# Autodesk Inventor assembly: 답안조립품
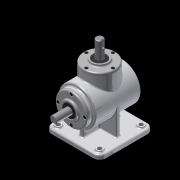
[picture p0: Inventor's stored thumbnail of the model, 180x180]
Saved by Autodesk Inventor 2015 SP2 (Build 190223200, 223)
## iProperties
Created: 2015-07
Part Number: 답안조립품
Document SubType Name: Assembly
Designer: AMC
Author: AMC
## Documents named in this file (14)
- C:\Users\AMC\Desktop\450705V1025\답안조립품.iam
- C:\Users\AMC\Desktop\450705V1025\본체.ipt
- C:\Users\AMC\Desktop\450705V1025\커버.ipt
- C:\Users\AMC\Desktop\450705V1025\베어링 6203.ipt
- C:\Users\AMC\Desktop\450705V1025\메인 베벨기어.ipt
- C:\Users\AMC\Desktop\450705V1025\메인 축.ipt
- 메인 축.ipt
- C:\Users\AMC\Desktop\450705V1025\키 5x5.ipt
- C:\Users\AMC\Desktop\450705V1025\서브 베벨기어.ipt
- C:\Users\AMC\Desktop\450705V1025\서브 축.ipt
- 서브 축.ipt
- C:\Users\AMC\Desktop\450705V1025\키 4x4.ipt
- C:\Users\AMC\Desktop\450705V1025\오일실.ipt
- C:\Users\AMC\Desktop\450705V1025\M4.ipt
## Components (8 placed, 1 different names)
1. M4:1
2. M4:3
3. M4:4
4. M4:5
5. M4:2
6. M4:6
7. M4:7
8. M4:8
